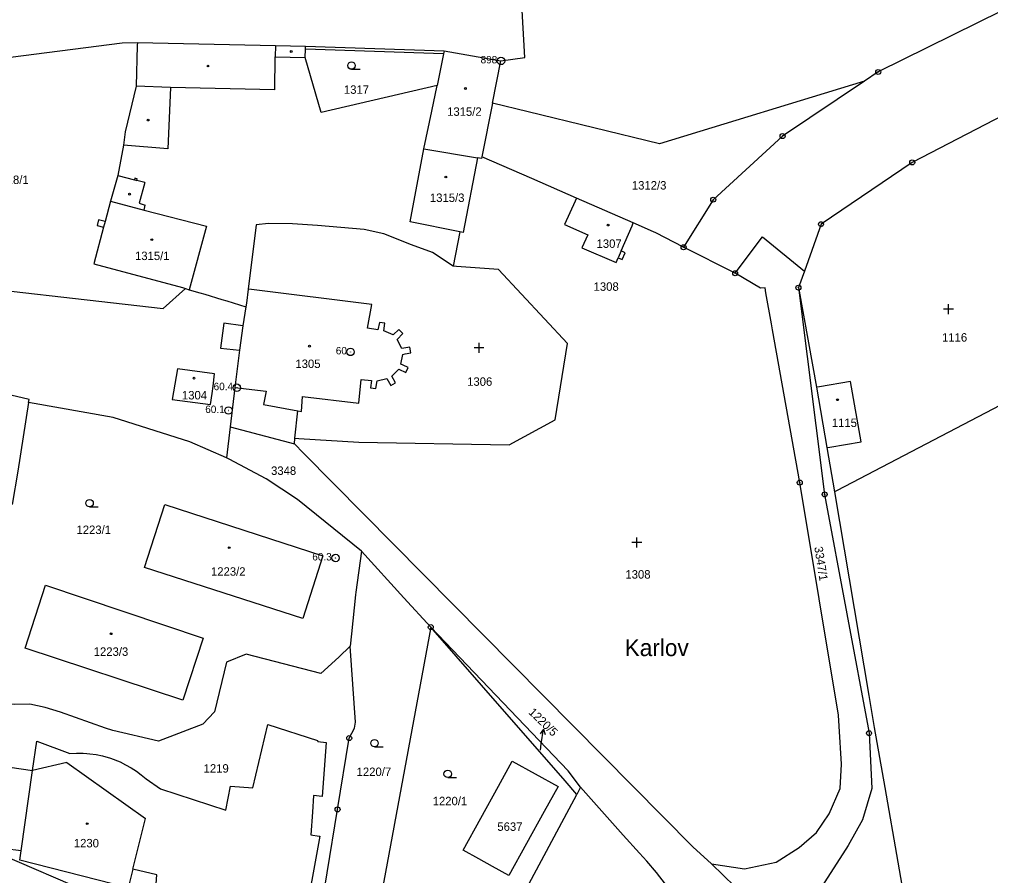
# Model space of a CAD drawing. Extents: x -733394 to -722299, y -1082822 to -1075049.
# Drawn here: x -728000 to -727804.6, y -1079117.6 to -1078945.4 of the extents above; entities that cross this region are included whole.
import ezdxf

# ---------------------------------------------------------------- set-up
doc = ezdxf.new("R2010")
doc.units = 0
for name, color, linetype in [('Hranice parcel', 7, 'Continuous'), ('Parcelní čísla', 7, 'Continuous'), ('Pop  PČ popisy', 7, 'Continuous'), ('Vnitřní kresba', 7, 'Continuous'), ('Značky bodu BP', 7, 'Continuous'), ('Značky budov', 7, 'Continuous'), ('Značky kultur', 7, 'Continuous')]:
    doc.layers.add(name, color=color, linetype=linetype)

msp = doc.modelspace()

# ---------------------------------------------------------------- linework, layer by layer
at = {"layer": 'Hranice parcel'}
for p, q in [((-727942.47, -1078950.72), (-727914.52, -1078951.65)), ((-727914.52, -1078951.65), (-727903.11, -1078953.7)), ((-727904.79, -1078962.2), (-727903.11, -1078953.7)), ((-727903.11, -1078953.7), (-727898.29, -1078952.98)), ((-727904.79, -1078962.2), (-727906.93, -1078972.97)), ((-727918.62, -1078971.39), (-727907.82, -1078973.18)), ((-727876.5, -1078986.31), (-727887.88, -1078981.32)), ((-727911.37, -1078988.1), (-727912.73, -1078994.99)), ((-727855.98, -1078996.43), (-727866.36, -1078991.19)), ((-727842.06, -1078995.97), (-727843.25, -1078999.32)), ((-727839.6, -1079019.35), (-727837.55, -1079031.51)), ((-727957.61, -1079027.34), (-727958.34, -1079033.56)), ((-727957.61, -1079027.34), (-727944.67, -1079030.77)), ((-727944.67, -1079030.77), (-727944.59, -1079029.61)), ((-727837.55, -1079031.51), (-727836, -1079040.38)), ((-727887.08, -1079099.81), (-727887.87, -1079101.29)), ((-727907.36, -1079137.64), (-727887.87, -1079101.29)), ((-727860.71, -1079115.28), (-727849.1, -1079126.54))]:
    msp.add_line(p, q, dxfattribs=at)
for points in [[(-727898.29, -1078952.98), (-727900.22, -1078919.85), (-727902.96, -1078872.93)], [(-727732.31, -1078902.48), (-727741.4, -1078910.35), (-727772.4, -1078928.8), (-727827.19, -1078955.93), (-727829.94, -1078957.77)], [(-728026.95, -1078956.18), (-727979.31, -1078950.06), (-727976.28, -1078950)], [(-727976.28, -1078950), (-727976.3, -1078950.6), (-727976.5, -1078958.8), (-727978.73, -1078967.98), (-727979.08, -1078970.66), (-727980.24, -1078976.74), (-727981.69, -1078981.94), (-727982.78, -1078986.01), (-727984.08, -1078985.66), (-727984.39, -1078986.83), (-727983.09, -1078987.17), (-727985.05, -1078994.52), (-727967.21, -1078999.31), (-727966.63, -1078999.46)], [(-727976.28, -1078950), (-727948.5, -1078950.62), (-727942.47, -1078950.72)], [(-727915.97, -1078958.63), (-727939.29, -1078964.05), (-727942.51, -1078952.98), (-727942.48, -1078951.37), (-727942.47, -1078950.72)], [(-727914.52, -1078951.65), (-727914.65, -1078952.29), (-727915.97, -1078958.63)], [(-727829.94, -1078957.77), (-727871.24, -1078970.36), (-727897.65, -1078963.94), (-727904.79, -1078962.2)], [(-727829.94, -1078957.77), (-727846.43, -1078968.82), (-727860.4, -1078981.62), (-727866.36, -1078991.19)], [(-727918.62, -1078971.39), (-727917.05, -1078963.83), (-727915.97, -1078958.63)], [(-727798.36, -1078962.74), (-727820.35, -1078974.12), (-727838.7, -1078986.55), (-727842.06, -1078995.97)], [(-727798.36, -1078962.74), (-727797.67, -1078964.82), (-727797.52, -1078965.4), (-727784.75, -1079013.62), (-727835.48, -1079040.11), (-727836, -1079040.38)], [(-727911.37, -1078988.1), (-727921.39, -1078986.1), (-727918.62, -1078971.39)], [(-727907.82, -1078973.18), (-727910.73, -1078988.2), (-727911.37, -1078988.1)], [(-727906.93, -1078972.97), (-727907, -1078973.31), (-727907.82, -1078973.18)], [(-727887.88, -1078981.32), (-727896.87, -1078977.38), (-727906.93, -1078972.97)], [(-727887.88, -1078981.32), (-727888.15, -1078981.91), (-727890.32, -1078986.64), (-727885.66, -1078988.66), (-727886.83, -1078991.29), (-727879.95, -1078994.24), (-727879.54, -1078993.31), (-727878.72, -1078993.67), (-727878.13, -1078992.3), (-727878.95, -1078991.94), (-727876.74, -1078986.86), (-727876.5, -1078986.31)], [(-727912.73, -1078994.99), (-727916.9, -1078992.24), (-727921.13, -1078990.73), (-727926.68, -1078988.46), (-727930.63, -1078987.64), (-727940.06, -1078986.8), (-727945.04, -1078986.45), (-727949.88, -1078986.42), (-727952.39, -1078986.67), (-727953.99, -1078999.61)], [(-727866.36, -1078991.19), (-727871.94, -1078988.28), (-727872.41, -1078988.1), (-727876.5, -1078986.31)], [(-727855.98, -1078996.43), (-727850.45, -1078989.12), (-727842.06, -1078995.97)], [(-727944.59, -1079029.61), (-727943.76, -1079029.66), (-727931.72, -1079030.44), (-727901.45, -1079030.97), (-727892.18, -1079025.89), (-727889.72, -1079010.53), (-727903.58, -1078995.67), (-727912.08, -1078995.04), (-727912.73, -1078994.99)], [(-727860.71, -1079115.28), (-727854.09, -1079116.27), (-727847.76, -1079114.88), (-727843.07, -1079111.96), (-727839.63, -1079108.95), (-727837.07, -1079105.18), (-727834.85, -1079100.07), (-727834.57, -1079095.18), (-727835.08, -1079087.52), (-727835.18, -1079085.36), (-727842.98, -1079038.54), (-727848.46, -1079007.83), (-727848.68, -1079006.63), (-727849.8, -1079000.35), (-727849.91, -1078999.34), (-727850.85, -1078999.42), (-727855.98, -1078996.43)], [(-728019.36, -1078998.04), (-727971.08, -1079003.54), (-727966.63, -1078999.46)], [(-727966.63, -1078999.46), (-727965.89, -1078999.73), (-727963.68, -1079000.36), (-727962.72, -1079000.65), (-727959.26, -1079001.7), (-727958.29, -1079001.99), (-727954.44, -1079003.16)], [(-727953.99, -1078999.61), (-727954.33, -1079002.46), (-727954.44, -1079003.16)], [(-727944.59, -1079029.61), (-727944, -1079024.12), (-727943.26, -1079024.26), (-727943.05, -1079021.22), (-727931.72, -1079022.56), (-727931.27, -1079017.79), (-727929.19, -1079018), (-727929.38, -1079019.45), (-727928.29, -1079019.61), (-727928.03, -1079018.04), (-727926.09, -1079017.61), (-727925.29, -1079019), (-727924.32, -1079018.49), (-727925.1, -1079017.16), (-727923.67, -1079015.7), (-727922.25, -1079016.36), (-727921.76, -1079015.38), (-727922.78, -1079014.9), (-727923.24, -1079014.69), (-727922.86, -1079012.76), (-727922.39, -1079012.66), (-727921.27, -1079012.43), (-727921.47, -1079011.31), (-727923.07, -1079011.58), (-727924, -1079009.78), (-727922.89, -1079008.56), (-727923.68, -1079007.76), (-727924.82, -1079008.78), (-727926.68, -1079008.03), (-727926.51, -1079006.48), (-727927.53, -1079006.31), (-727927.86, -1079007.84), (-727929.96, -1079007.49), (-727929.12, -1079002.68), (-727953.34, -1078999.69), (-727953.99, -1078999.61)], [(-727843.25, -1078999.32), (-727837.97, -1079040.92), (-727829.04, -1079088.96), (-727828.51, -1079100.1), (-727830.33, -1079106.39), (-727833.21, -1079111.58), (-727839.17, -1079120.76)], [(-727843.25, -1078999.32), (-727841.19, -1079010.43), (-727839.6, -1079019.35)], [(-727954.44, -1079003.16), (-727955.05, -1079006.97), (-727958.86, -1079006.47), (-727959.56, -1079011.49), (-727955.7, -1079011.89), (-727956.65, -1079019.4), (-727957.61, -1079027.34)], [(-727961.06, -1079019.11), (-727960.75, -1079016.67), (-727968.19, -1079015.63), (-727969.28, -1079021.83), (-727961.54, -1079022.84), (-727961.26, -1079020.63), (-727961.06, -1079019.11)], [(-727837.55, -1079031.51), (-727836.96, -1079031.41), (-727830.65, -1079030.35), (-727832.75, -1079018.17), (-727839.01, -1079019.25), (-727839.6, -1079019.35)], [(-727998.16, -1079022.43), (-727998.04, -1079021.82), (-728005.21, -1079020.14), (-728007.93, -1079019.51)], [(-727998.16, -1079022.43), (-728000.35, -1079036.26), (-728001.47, -1079042.97)], [(-727958.34, -1079033.56), (-727965.72, -1079030.32), (-727981.18, -1079025.43), (-727998.16, -1079022.43)], [(-727944.67, -1079030.77), (-727942.84, -1079032.62), (-727864.48, -1079111.81), (-727860.71, -1079115.28)], [(-727931.21, -1079052.36), (-727944.05, -1079041.93), (-727950.39, -1079037.78), (-727957.8, -1079033.8), (-727958.34, -1079033.56)], [(-727836, -1079040.38), (-727829.06, -1079081.41), (-727827.98, -1079087.8), (-727825.84, -1079099.89), (-727820.6, -1079129.91)], [(-727938.99, -1079053.29), (-727943, -1079065.92), (-727974.84, -1079055.6), (-727970.75, -1079042.96), (-727938.99, -1079053.29)], [(-727931.21, -1079052.36), (-727932.33, -1079060.58), (-727932.41, -1079061.15), (-727933.17, -1079068.96), (-727933.45, -1079071.42)], [(-727917.23, -1079067.62), (-727922.66, -1079061.74), (-727931.21, -1079052.36)], [(-727963.04, -1079069.84), (-727967.16, -1079082.32), (-727998.87, -1079071.88), (-727994.8, -1079059.2), (-727963.04, -1079069.84)], [(-727917.23, -1079067.62), (-727929.16, -1079132.12), (-727929.22, -1079133.03)], [(-727887.87, -1079101.29), (-727890.18, -1079098.54), (-727907.03, -1079079.3), (-727917.23, -1079067.62)], [(-727887.08, -1079099.81), (-727889.6, -1079096.55), (-727917.23, -1079067.62)], [(-727933.45, -1079071.42), (-727935.76, -1079073.69), (-727939.37, -1079076.92), (-727954.36, -1079073.04), (-727958.35, -1079074.68), (-727960.75, -1079084.68), (-727963.12, -1079087.13), (-727972, -1079090.59), (-727981.24, -1079088.42), (-727982.68, -1079087.94), (-727991.75, -1079084.73), (-727994.82, -1079083.8), (-727997.91, -1079083.15), (-728001.09, -1079083.16), (-728002.86, -1079083.06)], [(-727929.22, -1079133.03), (-727940.18, -1079129.8), (-727936, -1079104.3), (-727933.65, -1079089.95), (-727932.57, -1079087.92), (-727932.38, -1079086.72), (-727933.45, -1079071.42)], [(-727971.6, -1079100.13), (-727958.48, -1079104.48), (-727957.56, -1079099.6), (-727953.07, -1079099.97), (-727950.02, -1079087.19), (-727940.02, -1079090.44), (-727939.99, -1079090.61), (-727938.29, -1079090.81), (-727939.08, -1079101.69), (-727940.87, -1079101.53), (-727941.05, -1079104.88), (-727941.4, -1079109.39), (-727939.69, -1079109.69), (-727939.55, -1079109.71), (-727942.85, -1079127.7)], [(-728006.59, -1079095.15), (-727997.38, -1079096.5), (-727996.53, -1079090.58), (-727989.85, -1079093.06), (-727988.52, -1079092.98), (-727987.19, -1079092.99), (-727986.47, -1079093.03), (-727985.87, -1079093.09), (-727984.55, -1079093.27), (-727983.33, -1079093.52), (-727981.67, -1079094), (-727979.77, -1079094.74), (-727978.64, -1079095.3), (-727977.54, -1079095.92), (-727976.49, -1079096.61), (-727975.49, -1079097.36), (-727974.54, -1079098.16), (-727971.6, -1079100.13)], [(-727900.84, -1079094.59), (-727891.62, -1079099.69), (-727894.41, -1079104.73), (-727901.54, -1079117.6), (-727904.8, -1079115.79), (-727907.57, -1079114.26), (-727910.75, -1079112.5), (-727903.63, -1079099.63), (-727900.84, -1079094.59)], [(-727868.69, -1079165.76), (-727866.03, -1079155.6), (-727864.86, -1079149.7), (-727863.96, -1079143.97), (-727863.59, -1079137.98), (-727863.05, -1079132.15), (-727864, -1079129.3), (-727865.34, -1079126.59), (-727866.88, -1079124.02), (-727867.62, -1079122.79), (-727869.97, -1079119.35), (-727871.82, -1079116.98), (-727873.77, -1079114.69), (-727875.2, -1079113.08), (-727878.49, -1079109.45), (-727887.08, -1079099.81)], [(-728013.08, -1079108.76), (-728014.07, -1079111.26), (-728012.85, -1079111.71), (-728007.02, -1079113.88), (-728004, -1079113.23), (-727985.94, -1079121.04), (-727975.16, -1079125.64), (-727975.17, -1079126.04), (-727972.74, -1079126.14), (-727972.79, -1079128.64), (-727965.1, -1079130.67), (-727960.68, -1079131.37), (-727958.78, -1079132.09), (-727946.21, -1079137.35), (-727943.07, -1079137.48), (-727932.81, -1079141.56), (-727903.33, -1079153.8), (-727903.19, -1079153.32)], [(-727972.47, -1079119.24), (-727972.39, -1079117.45), (-727977.19, -1079116.33), (-727978.16, -1079120.08), (-727999.96, -1079114.49), (-727999.69, -1079112.6), (-728006.29, -1079111.84)]]:
    msp.add_lwpolyline(points, dxfattribs=at)
at = {"layer": 'Pop  PČ popisy'}
for p, q in [((-727894.57, -1079088.14), (-727895.21, -1079089.06)), ((-727894.99, -1079091.11), (-727894.57, -1079088.14)), ((-727894.57, -1079088.14), (-727894.22, -1079089.2)), ((-727895.16, -1079092.35), (-727894.99, -1079091.11))]:
    msp.add_line(p, q, dxfattribs=at)
at = {"layer": 'Vnitřní kresba'}
for p, q in [((-727948.5, -1078950.62), (-727948.54, -1078952.85)), ((-727914.65, -1078952.29), (-727942.48, -1078951.37)), ((-727948.65, -1078959.55), (-727948.54, -1078952.85)), ((-727948.54, -1078952.85), (-727942.51, -1078952.98)), ((-727969.6, -1078959.08), (-727976.5, -1078958.8)), ((-727969.6, -1078959.08), (-727970.16, -1078971.42)), ((-727948.65, -1078959.55), (-727969.6, -1078959.08)), ((-727970.16, -1078971.42), (-727979.08, -1078970.66)), ((-727980.24, -1078976.74), (-727976.88, -1078977.63)), ((-727976.79, -1078977.31), (-727976.88, -1078977.63)), ((-727976.31, -1078977.44), (-727976.79, -1078977.31)), ((-727976.88, -1078977.63), (-727976.39, -1078977.76)), ((-727976.39, -1078977.76), (-727976.31, -1078977.44)), ((-727974.77, -1078978.19), (-727976.39, -1078977.76)), ((-727974.77, -1078978.19), (-727975.91, -1078982.34)), ((-727981.69, -1078981.94), (-727974.89, -1078983.72)), ((-727975.91, -1078982.34), (-727974.69, -1078982.7)), ((-727974.89, -1078983.72), (-727974.69, -1078982.7)), ((-727974.89, -1078983.72), (-727962.34, -1078986.97)), ((-727982.78, -1078986.01), (-727983.09, -1078987.17)), ((-727962.34, -1078986.97), (-727965.89, -1078999.73)), ((-727878.95, -1078991.94), (-727879.54, -1078993.31)), ((-727955.05, -1079006.97), (-727955.7, -1079011.89)), ((-727956.65, -1079019.4), (-727950.37, -1079020.18)), ((-727950.37, -1079020.18), (-727950.88, -1079022.85)), ((-727950.88, -1079022.85), (-727944, -1079024.12)), ((-727999.69, -1079112.6), (-727997.38, -1079096.5)), ((-727990.48, -1079094.86), (-727997.38, -1079096.5)), ((-727990.48, -1079094.86), (-727974.62, -1079106.11)), ((-727977.19, -1079116.33), (-727974.62, -1079106.11))]:
    msp.add_line(p, q, dxfattribs=at)
at = {"layer": 'Značky bodu BP'}
for centre, radius in [((-727903.11, -1078953.7), 0.75), ((-727903.11, -1078953.7), 0.03), ((-727827.19, -1078955.93), 0.5), ((-727827.19, -1078955.93), 0.0303), ((-727846.43, -1078968.82), 0.5), ((-727846.43, -1078968.82), 0.0303), ((-727820.35, -1078974.12), 0.5), ((-727820.35, -1078974.12), 0.0303), ((-727860.4, -1078981.62), 0.5), ((-727860.4, -1078981.62), 0.0303), ((-727838.7, -1078986.55), 0.5), ((-727838.7, -1078986.55), 0.0303), ((-727866.36, -1078991.19), 0.5), ((-727866.36, -1078991.19), 0.0303), ((-727855.98, -1078996.43), 0.5), ((-727855.98, -1078996.43), 0.0303), ((-727843.25, -1078999.32), 0.5), ((-727843.25, -1078999.32), 0.0303), ((-727933.39, -1079012.25), 0.75), ((-727933.39, -1079012.25), 0.03), ((-727956.26, -1079019.45), 0.75), ((-727956.26, -1079019.45), 0.03), ((-727957.95, -1079024.04), 0.75), ((-727957.95, -1079024.04), 0.03), ((-727842.98, -1079038.54), 0.5), ((-727842.98, -1079038.54), 0.0303), ((-727837.97, -1079040.92), 0.5), ((-727837.97, -1079040.92), 0.0303), ((-727936.4, -1079053.71), 0.75), ((-727936.4, -1079053.71), 0.03), ((-727917.23, -1079067.62), 0.5), ((-727917.23, -1079067.62), 0.0303), ((-727829.04, -1079088.96), 0.5), ((-727933.65, -1079089.95), 0.5), ((-727933.65, -1079089.95), 0.0303), ((-727829.04, -1079088.96), 0.0303), ((-727936, -1079104.3), 0.5), ((-727936, -1079104.3), 0.0303)]:
    msp.add_circle(centre, radius, dxfattribs=at)
at = {"layer": 'Značky budov'}
for centre in [(-727945.32, -1078951.8), (-727962.08, -1078954.73), (-727910.26, -1078959.25), (-727974.13, -1078965.61), (-727914.2, -1078977.06), (-727977.85, -1078980.51), (-727881.54, -1078986.73), (-727973.38, -1078989.67), (-727941.64, -1079011.09), (-727964.88, -1079017.53), (-727835.38, -1079021.88), (-727957.79, -1079051.63), (-727981.57, -1079068.96), (-727986.37, -1079107.17)]:
    msp.add_circle(centre, 0.175, dxfattribs=at)
at = {"layer": 'Značky kultur'}
for p, q in [((-727933.19, -1078955.39), (-727931.44, -1078955.39)), ((-727813.06, -1079004.67), (-727813.06, -1079002.67)), ((-727812.06, -1079003.67), (-727814.06, -1079003.67)), ((-727907.53, -1079012.45), (-727907.53, -1079010.45)), ((-727906.53, -1079011.45), (-727908.53, -1079011.45)), ((-727985.9, -1079043.43), (-727984.15, -1079043.43)), ((-727875.79, -1079051.6), (-727875.79, -1079049.6)), ((-727874.79, -1079050.6), (-727876.79, -1079050.6)), ((-727928.56, -1079091.71), (-727926.81, -1079091.71)), ((-727913.83, -1079097.9), (-727912.08, -1079097.9))]:
    msp.add_line(p, q, dxfattribs=at)
for centre in [(-727933.19, -1078954.64), (-727985.9, -1079042.68), (-727928.56, -1079090.96), (-727913.83, -1079097.15)]:
    msp.add_circle(centre, 0.75, dxfattribs=at)

# ---------------------------------------------------------------- texts
at = {"layer": 'Parcelní čísla'}
for s, p in [('1317', (-727934.72, -1078960.32)), ('1315/2', (-727913.95, -1078964.75)), ('1318/1', (-728005.11, -1078978.47)), ('1312/3', (-727876.77, -1078979.58)), ('1315/3', (-727917.41, -1078982.08)), ('1307', (-727883.88, -1078991.31)), ('1315/1', (-727976.76, -1078993.77)), ('1308', (-727884.47, -1078999.95)), ('1116', (-727814.35, -1079010.18)), ('1305', (-727944.48, -1079015.49)), ('1306', (-727909.92, -1079019.07)), ('1304', (-727967.32, -1079021.81)), ('1115', (-727836.53, -1079027.36)), ('3348', (-727949.38, -1079036.99)), ('1223/1', (-727988.54, -1079048.89)), ('1223/2', (-727961.47, -1079057.28)), ('1308', (-727878.07, -1079057.86)), ('1223/3', (-727985.07, -1079073.4)), ('1219', (-727962.95, -1079096.9)), ('1220/7', (-727932.16, -1079097.58)), ('1220/1', (-727916.85, -1079103.46)), ('5637', (-727903.84, -1079108.61)), ('1230', (-727989.07, -1079111.94))]:
    msp.add_text(s, height=1.7, dxfattribs=at).set_placement(p)
for s, rotation, p in [('3347/1', 279, (-727840.07, -1079051.54)), ('1220/5', 316, (-727897.68, -1079084.91))]:
    msp.add_text(s, height=1.7, rotation=rotation, dxfattribs=at).set_placement(p)
at = {"layer": 'Pop  PČ popisy'}
msp.add_text('Karlov', height=3.4, dxfattribs=at).set_placement((-727878.21, -1079073.46))
at = {"layer": 'Značky bodu BP'}
for s, p in [('898', (-727907.21, -1078954.2)), ('60', (-727936.35, -1079012.75)), ('60.4', (-727960.94, -1079019.95)), ('60.1', (-727962.62, -1079024.54)), ('60.3', (-727941.08, -1079054.21))]:
    msp.add_text(s, height=1.5, dxfattribs=at).set_placement(p)

doc.saveas('drawing.dxf')
